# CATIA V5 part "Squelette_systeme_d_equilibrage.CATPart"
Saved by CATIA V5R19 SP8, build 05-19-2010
Part number: Squelette_systeme_d_equilibrage
Bounding box of the stored display mesh (mm): x -127 to 127, y -600 to 30, z 1197.5 to 1315
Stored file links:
  G:\EU_thinkMotion\CFAO_2010\MMS_groupe2\MMS_groupe2\OK\nrosalie\nrosalie_cfao_support_d_arme_legere_final\Squelette_systeme_d_equilibrage.CATPart
  G:\EU_thinkMotion\CFAO_2010\MMS_groupe2\MMS_groupe2\OK\nrosalie\nrosalie_cfao_support_d_arme_legere_final\nrosalie_Support_d_arme_legere.CATProduct
  G:\EU_thinkMotion\CFAO_2010\MMS_groupe2\MMS_groupe2\OK\nrosalie\nrosalie_cfao_support_d_arme_legere_final\Squelette_bras.CATPart
  G:\EU_thinkMotion\CFAO_2010\MMS_groupe2\MMS_groupe2\OK\nrosalie\nrosalie_cfao_support_d_arme_legere_final\Squelette_piece_support.CATPart
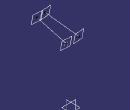
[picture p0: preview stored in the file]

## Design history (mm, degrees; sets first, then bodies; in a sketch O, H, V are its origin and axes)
External parameters (linked from other documents)
  External.Pourcentage_de_la_position_de_l_equilibrage_sur_la_piece_de_support_en_partant_axe_pivot_verticale = 10
Set1
  Line1: type PtPt, FirstPoint Point1, SecondPoint DatumPoint2
  Plane1: type Normal, Curve Line1, RefPoint vertex of Line1
  Plane2: type Normal, Curve Line1, RefPoint Point1
Set2
  DatumPoint1: linked copy from another document
  DatumPoint2: linked copy from another document
  Point1: linked copy from another document
  Line2: linked copy from another document
  Line3: linked copy from another document
  Point2: linked copy from another document
  DatumPoint3: linked copy from another document
Body1 (main body)
  Point3: type OnCurve, Support Line3, RefPoint Point2, Ratio 0.1 {= External.Pourcentage_de_la_position_de_l_equilibrage_sur_la_piece_de_support_en_partant_axe_pivot_verticale /100}
  Line4: type PtPt, FirstPoint Point3, SecondPoint DatumPoint3
  Plane3: type Normal, Curve Line4, RefPoint vertex of Line4
  Plane4: type Normal, Curve Line4, RefPoint Point3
